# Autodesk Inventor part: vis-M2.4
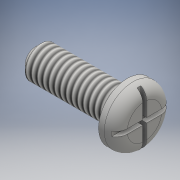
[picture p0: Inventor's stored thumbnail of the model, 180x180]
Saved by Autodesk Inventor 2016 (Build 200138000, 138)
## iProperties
Created: 2018-03
Part Number: vis-M2.4
Material: Générique
Document SubType Name: Modeling
Designer: Bruno
Density: 1 g/cm^3
Appearance: Par défaut
Author: Bruno
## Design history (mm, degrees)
sketch "Esquisse1"
  geometry: C1 r 1.4 at (0, 0); 1 further point
  constraints: 1 centre point, 1 coincident
  dimensions: "d0" = 2.8 diameter of C1
extrude "Extrusion1" new body sketch "Esquisse1" distance "d1" = 8; taper "d2" = 0 deg
sketch "Esquisse2"
  geometry: C1 r 2.5 at (0, 0); 1 further point
  constraints: 1 centre point, 1 coincident
  dimensions: "d3" = 5 diameter of C1
extrude "Extrusion2" join sketch "Esquisse2" distance "d4" = 1.5; taper "d5" = 0 deg
fillet "Congé1" dims "d6" = 1
sketch "Esquisse3"
  geometry: L1 (-0.204, 3.169)-(0.204, 3.169); L2 (0.204, 3.169)-(0.204, -3.51); L3 (0.204, -3.51)-(-0.204, -3.51); L4 (-0.204, -3.51)-(-0.204, 3.169); L5 (-2.999, 0.183)-(3.203, 0.183); L6 (3.203, 0.183)-(3.203, -0.161); L7 (3.203, -0.161)-(-2.999, -0.161); L8 (-2.999, -0.161)-(-2.999, 0.183); 1 further point
  constraints: 16 end point, 4 parallel, 2 horizontal, 2 perpendicular
extrude "Extrusion3" cut sketch "Esquisse3" distance "d7" = 0.5; taper "d8" = 0 deg
chamfer "Chanfrein1" distance "d9" = 0.5; stored, may be unused: second distance "d10" = 2, angle "d11" = 45 deg
feature "Filetage1" dims "d12" = 10, "d13" = 0
node "Solide1"
